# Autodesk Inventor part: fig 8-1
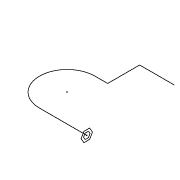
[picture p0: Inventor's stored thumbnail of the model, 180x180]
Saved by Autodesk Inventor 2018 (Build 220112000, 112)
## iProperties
Created: 2004-05
Part Number: fig 8-1
Document SubType Name: Modeling
Designer: CADCIM Technologies
Manufacturer: Standard
Standards Organization: Custom
Density: 1 g/cm^3
Material: Generic
Appearance: Default
Author: CADCIM Technologies
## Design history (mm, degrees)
sketch "Sketch1"
  geometry: L1 (-42.583, 3.219)-(-90.066, 3.219); L2 (-90.066, 58.92)-(-77.282, 58.92); L3 (-77.282, 58.92)-(-77.282, 91.063); L4 (-77.282, 91.063)-(-42.583, 91.063); A1 r 27.851 centre (-90.066, 31.07) between (-90.066, 58.92) and (-90.066, 3.219)
  constraints: 8 end point, 2 parallel, 2 point on circle, 2 tangent, 1 centre point, 1 perpendicular
workplane "Work Plane2"
sketch "Sketch2"
  geometry: L1 (-5.697, 0)-(-2.849, 4.934); L2 (-2.849, 4.934)-(2.849, 4.934); L3 (2.849, 4.934)-(5.697, 0); L4 (5.697, 0)-(2.849, -4.934); L5 (2.849, -4.934)-(-2.849, -4.934); L6 (-2.849, -4.934)-(-5.697, 0); L7 (-3.256, 0)-(-1.628, 2.819); L8 (-1.628, 2.819)-(1.628, 2.819); L9 (1.628, 2.819)-(3.256, 0); L10 (3.256, 0)-(1.628, -2.819); L11 (1.628, -2.819)-(-1.628, -2.819); L12 (-1.628, -2.819)-(-3.256, 0); 2 further points
  constraints: 24 end point, 1 coincident, 22 other
